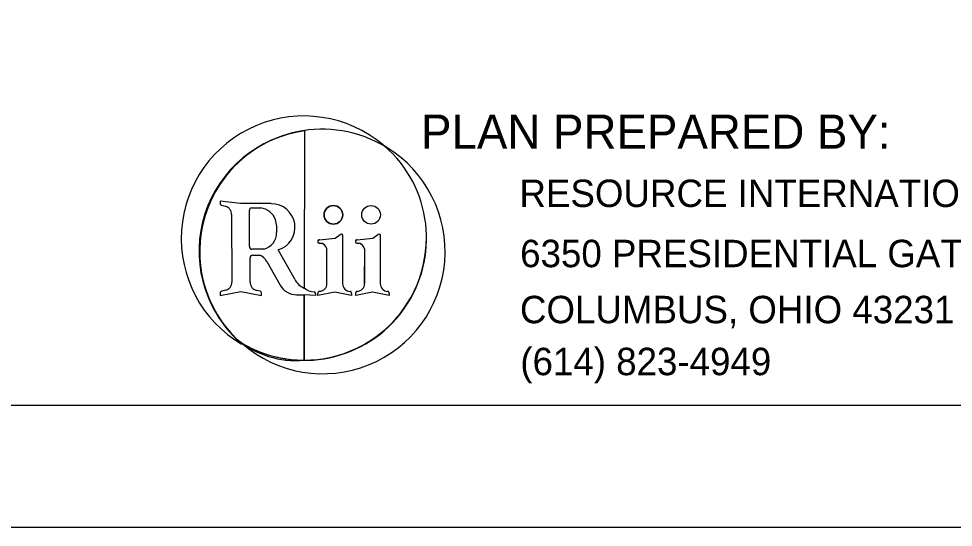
# Model space of a CAD drawing. Extents: x 0 to 91.3, y -0.7 to 22.
# Drawn here: x 1.963 to 5.794, y 0 to 2.086 of the extents above; entities that cross this region are included whole.
import ezdxf

# ---------------------------------------------------------------- set-up
doc = ezdxf.new("R2010")
doc.units = 0
for name, color, linetype in [('Default', 7, 'Continuous'), ('SH_Border', 7, 'Continuous'), ('SH_Cut_Line', 7, 'Continuous'), ('SH_Text', 7, 'Continuous')]:
    doc.layers.add(name, color=color, linetype=linetype)

msp = doc.modelspace()

# ---------------------------------------------------------------- linework, layer by layer
at = {"layer": 'Default'}
for p, q in [((3.1348, 1.626), (3.1331, 0.9817)), ((3.457, 1.5684), (3.4657, 1.5616)), ((3.472, 1.5583), (3.4616, 1.5652)), ((2.7934, 1.3213), (2.81, 1.3168)), ((2.8358, 1.2825), (2.8364, 1.0059)), ((2.909, 1.1514), (2.9089, 1.2997)), ((3.4453, 1.1949), (3.4451, 1.1458)), ((2.9677, 1.141), (2.9195, 1.1409)), ((2.9222, 1.1164), (2.9509, 1.1164)), ((3.0946, 1.0177), (3.0272, 1.1379)), ((3.2266, 0.9997), (3.2269, 1.1424)), ((3.3811, 0.9997), (3.3814, 1.1424)), ((3.3814, 0.9997), (3.3814, 1.1424)), ((3.4451, 1.1458), (3.4451, 0.9997)), ((2.9117, 1.0059), (2.9116, 1.1058)), ((2.9807, 1.0897), (3.0344, 0.9937)), ((2.8099, 0.9727), (2.7956, 0.9681)), ((2.9524, 0.9681), (2.938, 0.9717)), ((3.1331, 0.9532), (3.1331, 0.6858)), ((3.1331, 0.6858), (3.1331, 0.9532)), ((3.1331, 0.6858), (3.1331, 0.9532))]:
    msp.add_line(p, q, dxfattribs=at)
for points in [[(2.9987, 1.3276), (2.8729, 1.3276), (2.7893, 1.3375), (2.7886, 1.3284)], [(2.9171, 1.3102), (2.9195, 1.3102), (2.9558, 1.3102)], [(3.196, 1.1787), (3.2602, 1.1863), (3.2809, 1.2007)], [(3.2909, 1.1949), (3.2909, 1.1949), (3.2906, 0.9997)], [(3.3503, 1.1787), (3.4147, 1.1863), (3.4354, 1.2007)], [(3.4453, 1.1949), (3.4453, 1.1949), (3.4451, 0.9997)], [(2.7889, 0.9597), (2.7893, 0.951), (2.8741, 0.9679), (2.9587, 0.951), (2.9587, 0.9594)], [(3.3274, 0.9594), (3.3277, 0.951), (3.2588, 0.9646), (3.19, 0.951), (3.19, 0.9594)], [(3.482, 0.9594), (3.482, 0.951), (3.4132, 0.9646), (3.3445, 0.951), (3.3445, 0.9594)], [(3.4817, 0.9594), (3.482, 0.951), (3.4132, 0.9646), (3.3445, 0.951), (3.3445, 0.9594)], [(3.1021, 0.954), (3.1331, 0.9532), (3.1331, 0.6858)], [(3.1802, 0.9574), (3.1804, 0.951), (3.1331, 0.9532)]]:
    msp.add_lwpolyline(points, dxfattribs=at)
for centre in [(3.2533, 1.2819), (3.4077, 1.2819)]:
    msp.add_circle(centre, 0.0381, dxfattribs=at)
for centre, radius, start, end in [((3.1322, 1.1846), 0.5027, 49.7678, 239.5027), ((3.2, 1.1327), 0.4975, 97.5272, 226.4723), ((3.2075, 1.1303), 0.5027, 59.0935, 228.9029), ((3.2071, 1.1309), 0.5019, 98.4724, 227.2599), ((3.2071, 1.1309), 0.5019, 98.4724, 227.2599), ((3.2071, 1.1309), 0.5019, 98.4724, 153.6811), ((3.2071, 1.1309), 0.5019, 98.4724, 153.6811), ((3.134, 1.1861), 0.5011, 239.4981, 49.1524), ((3.21, 1.1311), 0.5011, 228.7568, 58.4918), ((2.7969, 1.3289), 0.00832, 182.5897, 244.5009), ((2.8017, 1.2837), 0.0342, 357.9979, 75.7411), ((2.92, 1.2995), 0.011, 105.7103, 179.2881), ((2.9458, 1.2371), 0.0738, 19.667, 82.164), ((2.9989, 1.2306), 0.0969, 286.969, 90.1401), ((3.2533, 1.2819), 0.0381, 360, 180), ((3.2533, 1.2819), 0.0381, 360, 180), ((3.2533, 1.2819), 0.0381, 180, 0), ((3.2533, 1.2819), 0.0381, 180, 0), ((2.9192, 1.2255), 0.1028, 350.7227, 20.79), ((2.9503, 1.2092), 0.0703, 284.3032, 359.7161), ((3.2857, 1.1944), 0.00786, 50.974, 127.0153), ((3.2858, 1.1937), 0.00847, 64.2158, 124.5765), ((3.2876, 1.1975), 0.00423, 320.8562, 64.2158), ((3.2879, 1.1976), 0.00404, 319.407, 46.4158), ((3.4401, 1.1944), 0.00786, 50.974, 127.0153), ((3.4402, 1.1937), 0.00847, 64.2158, 124.5765), ((3.4421, 1.1975), 0.00423, 320.8562, 64.2158), ((3.4423, 1.1976), 0.00404, 319.407, 46.4158), ((2.9187, 1.1506), 0.00967, 174.4637, 274.9007), ((3.1332, 1.1869), 0.5011, 256.9569, 360), ((3.1955, 1.1729), 0.00635, 87.1899, 182.7762), ((3.1966, 1.1729), 0.00741, 182.7762, 282.1194), ((3.1962, 1.1718), 0.00688, 92.6227, 269.9386), ((3.1976, 1.1347), 0.0302, 14.6267, 92.6818), ((3.1962, 1.134), 0.0318, 15.2292, 86.4844), ((3.35, 1.1729), 0.00635, 87.1899, 182.7762), ((3.351, 1.1729), 0.00741, 182.7762, 282.1194), ((3.3506, 1.1718), 0.00688, 92.6227, 269.9386), ((3.352, 1.1347), 0.0302, 14.6267, 92.6818), ((3.3506, 1.134), 0.0318, 15.2292, 86.4844), ((2.9222, 1.1058), 0.0106, 90, 180), ((2.9279, 1.0608), 0.0602, 28.5907, 67.4831), ((2.8042, 1.0045), 0.0324, 280.2793, 2.7167), ((2.9468, 1.0057), 0.0351, 179.5117, 255.4532), ((3.1611, 1.0502), 0.074, 206.0561, 247.8371), ((3.1951, 0.9998), 0.0317, 272.1673, 0), ((3.1948, 0.9996), 0.0318, 272.8276, 0.2641), ((3.3228, 0.9995), 0.0321, 179.4418, 267.2388), ((3.3492, 0.9996), 0.0318, 272.8276, 0.2641), ((3.4772, 0.9995), 0.0321, 179.4418, 267.2388), ((2.7959, 0.9609), 0.00718, 91.7779, 189.4641), ((2.9514, 0.9607), 0.00741, 349.3806, 82.7779), ((3.1041, 1.0345), 0.0807, 210.3808, 268.5526), ((3.1768, 1.0328), 0.0672, 229.5343, 267.7938), ((3.1742, 0.9594), 0.00625, 341.7132, 90.444), ((3.1972, 0.9607), 0.00741, 97.2221, 190.6198), ((3.1969, 0.9608), 0.00707, 94.4974, 191.9747), ((3.3214, 0.9613), 0.00617, 342.8575, 91.0183), ((3.3513, 0.9608), 0.00707, 94.4974, 191.9747), ((3.3517, 0.9607), 0.00741, 97.2221, 190.6198), ((3.4748, 0.9607), 0.00741, 349.3802, 82.7779), ((3.4758, 0.9613), 0.00617, 342.8575, 91.0183), ((3.0972, 1.0547), 0.3706, 229.6875, 275.5683), ((3.1335, 1.19), 0.5042, 238.0215, 269.9593), ((3.1335, 1.19), 0.5042, 238.0215, 269.9593)]:
    msp.add_arc(centre, radius, start, end, dxfattribs=at)
at = {"layer": 'SH_Border'}
msp.add_lwpolyline([(1.5, 21.5), (33.5, 21.5), (33.5, 0.5), (1.5, 0.5)], close=True, dxfattribs=at)
at = {"layer": 'SH_Cut_Line'}
msp.add_lwpolyline([(0, 0), (34, 0), (34, 22), (0, 22)], close=True, dxfattribs=at)

# ---------------------------------------------------------------- texts
at = {"layer": 'Default'}
for s, p in [('RESOURCE INTERNATIONAL INC.', (4.0159, 1.3139)), ('6350 PRESIDENTIAL GATEWAY', (4.0187, 1.067)), ('COLUMBUS, OHIO 43231', (4.0179, 0.8371)), ('(614) 823-4949', (4.0194, 0.624))]:
    msp.add_text(s, height=0.1125, dxfattribs=at).set_placement(p)
at = {"layer": 'SH_Text'}
msp.add_text('PLAN PREPARED BY:', height=0.14, dxfattribs=at).set_placement((3.6125, 1.553))

doc.saveas('drawing.dxf')
